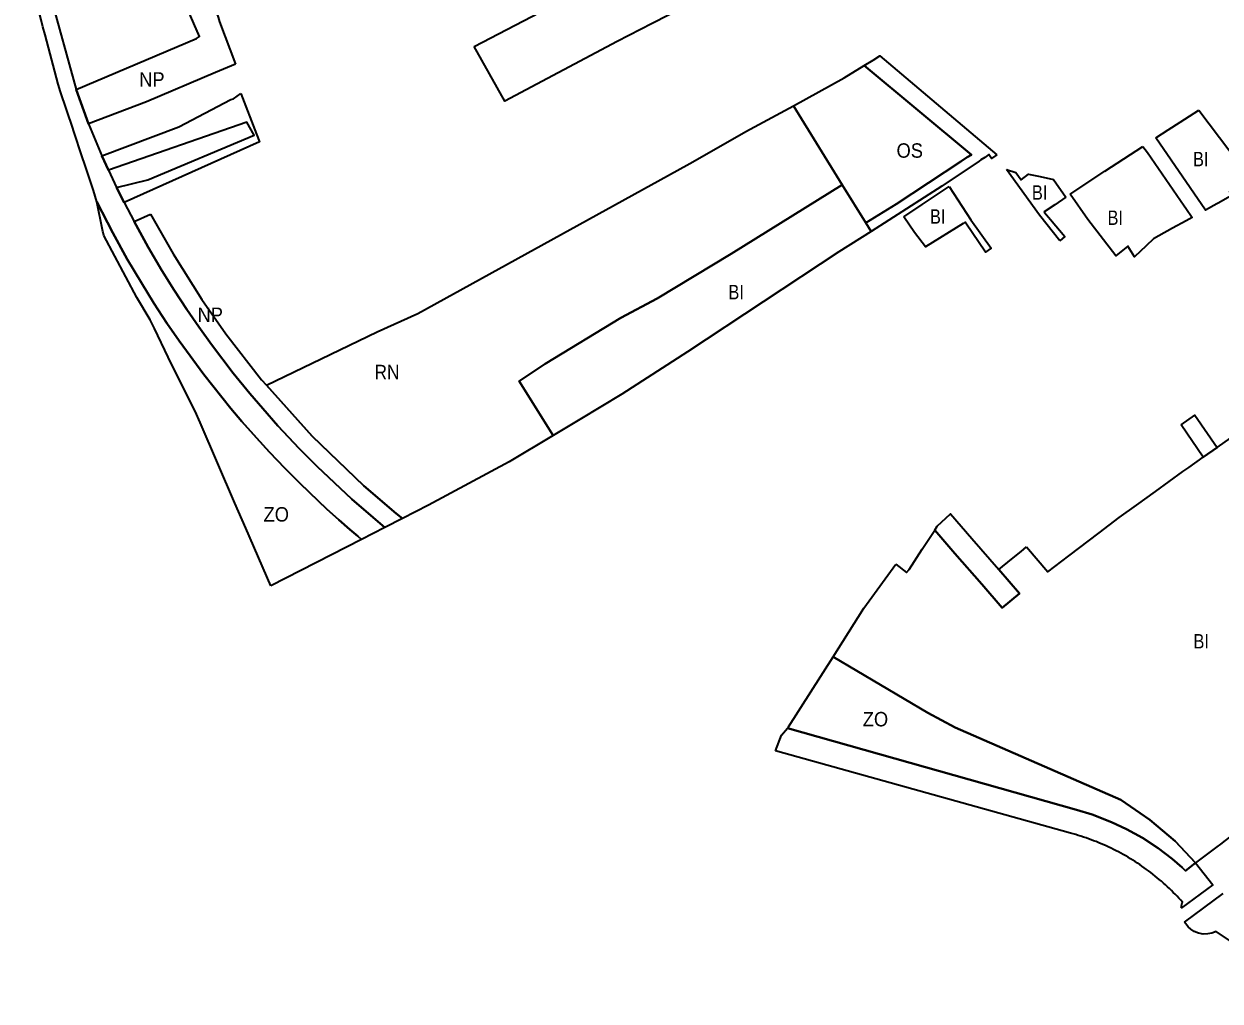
# Model space of a CAD drawing. Extents: x -650971 to -642489, y -1074311 to -1062745.
# Drawn here: x -649069 to -648072, y -1071514 to -1070700 of the extents above; entities that cross this region are included whole.
import ezdxf

# ---------------------------------------------------------------- set-up
doc = ezdxf.new("R2010")
doc.units = 0
doc.header["$LTSCALE"] = 4.8
for name, color, linetype, lineweight in [('15', 7, 'Continuous', 35), ('2', 7, 'Continuous', 35), ('24', 7, 'Continuous', 35), ('42', 7, 'Continuous', 35), ('48', 7, 'Continuous', 35), ('62', 7, 'Continuous', 35), ('7', 7, 'Continuous', 35), ('9', 7, 'Continuous', 35)]:
    doc.layers.add(name, color=color, linetype=linetype, lineweight=lineweight)

msp = doc.modelspace()

# ---------------------------------------------------------------- linework, layer by layer
at = {"layer": '15'}
for points in [[(-648368.163, -1070734.376), (-648360.83, -1070729.87), (-648355.275, -1070726.455), (-648257.61, -1070808.91)], [(-648366.98, -1070865.44), (-648341.58, -1070849.98), (-648287.74, -1070814.32), (-648282.44, -1070810.84), (-648278.832, -1070808.761), (-648368.163, -1070734.376)], [(-648257.61, -1070808.91), (-648262.15, -1070811.96), (-648264.38, -1070808.66), (-648267.8, -1070810.96), (-648271.1, -1070813.17), (-648272.453, -1070814.072), (-648272.45, -1070814.075), (-648303.631, -1070834.849), (-648362.519, -1070872.788), (-648366.98, -1070865.44)], [(-648309.41, -1071121.655), (-648307.33, -1071118.47), (-648296.34, -1071108.04), (-648278.39, -1071128.74), (-648256.04, -1071154.5)], [(-648256.04, -1071154.5), (-648238.84, -1071174.33), (-648253.126, -1071186.542), (-648270.236, -1071166.815), (-648292.587, -1071141.054), (-648309.41, -1071121.655)]]:
    msp.add_lwpolyline(points, dxfattribs=at)
msp.add_lwpolyline([(-648104.12, -1071033.78), (-648092.72, -1071025.89), (-648074.121, -1071052.749), (-648085.73, -1071060.92)], close=True, dxfattribs=at)
at = {"layer": '2'}
for points in [[(-648125.2, -1070794.79), (-648114.77, -1070788.08), (-648104.78, -1070781.65), (-648089.27, -1070771.57)], [(-648089.27, -1070771.57), (-648047.17, -1070827.35), (-648056.61, -1070834.26), (-648063.76, -1070839.49), (-648061.52, -1070842.68), (-648065.35, -1070844.8), (-648072.59, -1070848.79), (-648074.41, -1070849.79), (-648083.65, -1070854.89), (-648125.2, -1070794.79)], [(-648196.65, -1070841.7), (-648167.6, -1070822.53), (-648151.77, -1070812.11), (-648136.08, -1070801.79)], [(-648136.08, -1070801.79), (-648132.03, -1070807.05), (-648101.45, -1070851.34), (-648100, -1070853.35), (-648094.9, -1070861.09), (-648099.85, -1070863.82), (-648111.24, -1070870.11), (-648122.72, -1070876.44), (-648127, -1070878.75), (-648133.14, -1070884.6), (-648142.79, -1070893.78), (-648148.34, -1070884.92), (-648158.58, -1070892.98), (-648181.75, -1070862.74), (-648196.65, -1070841.7)], [(-648249.5, -1070821.08), (-648241.96, -1070823.46), (-648237.46, -1070829.68), (-648231.22, -1070824.92), (-648221.58, -1070827.03), (-648210.517, -1070829.445), (-648200.17, -1070844.094)], [(-648205.18, -1070880.5), (-648222.158, -1070859.221), (-648249.5, -1070821.08)], [(-648627.39, -1071042.65), (-648655.76, -1070997.5), (-648634.07, -1070983.17), (-648571.14, -1070944.67), (-648540.7, -1070928.6), (-648479.18, -1070891.26), (-648386.587, -1070833.807), (-648366.98, -1070865.44), (-648362.519, -1070872.788)], [(-648335.19, -1070860.49), (-648320.02, -1070850.16), (-648297.39, -1070835.36)], [(-648297.39, -1070835.36), (-648279.39, -1070862.98), (-648262.4, -1070886.58), (-648267.24, -1070889.9), (-648283.46, -1070865.74), (-648284.02, -1070864.91), (-648285.72, -1070865.96), (-648317.14, -1070885.48), (-648326.41, -1070873.55), (-648335.19, -1070860.49)], [(-648200.17, -1070844.094), (-648209.37, -1070850.44), (-648218.11, -1070856.44), (-648217.85, -1070856.93), (-648212.94, -1070862.74), (-648200.86, -1070877.05), (-648205.18, -1070880.5)], [(-648362.519, -1070872.788), (-648389.33, -1070889.79), (-648515.46, -1070972.94), (-648570.23, -1071008.2), (-648605.3, -1071029.34), (-648627.39, -1071042.65)], [(-648074.121, -1071052.749), (-648062.53, -1071044.59), (-648051.48, -1071036.97), (-648044.82, -1071032.25), (-648030.24, -1071021.91), (-648008.34, -1071006.32), (-647988.81, -1070993.27), (-647970.19, -1070980.45), (-647952.01, -1070967.82), (-647934.9, -1070955.87), (-647913.45, -1070940.79)], [(-648232.8, -1071135.6), (-648215.08, -1071156.35), (-648197.57, -1071143.03), (-648172.48, -1071123.95), (-648155.77, -1071111.23), (-648141.12, -1071100.71), (-648125.53, -1071089.51), (-648102.55, -1071072.86), (-648097.61, -1071069.37), (-648085.73, -1071060.92), (-648074.121, -1071052.749)], [(-648341.943, -1071150.071), (-648333.002, -1071157.07), (-648330.78, -1071154.36), (-648319.77, -1071137.52), (-648309.41, -1071121.655)], [(-648309.41, -1071121.655), (-648292.587, -1071141.054), (-648270.236, -1071166.815), (-648253.126, -1071186.542), (-648238.84, -1071174.33), (-648256.04, -1071154.5), (-648245.49, -1071145.91)], [(-648245.49, -1071145.91), (-648237.46, -1071139.38), (-648232.8, -1071135.6)], [(-648394.104, -1071227.17), (-648368.48, -1071186.81), (-648341.943, -1071150.071)], [(-648091.92, -1071399.07), (-648109, -1071381), (-648130, -1071363), (-648154.21, -1071346.477), (-648292.406, -1071286.112), (-648315.127, -1071274.052), (-648394.104, -1071227.17)], [(-647965.26, -1071302.86), (-647994.31, -1071325.03), (-648009.31, -1071336.48), (-648025.39, -1071348.76), (-648038.18, -1071358.51), (-648060.01, -1071374.69), (-648067.27, -1071380.27), (-648071.17, -1071383.26), (-648074.27, -1071385.62), (-648091.92, -1071399.07)]]:
    msp.add_lwpolyline(points, dxfattribs=at)
at = {"layer": '24'}
msp.add_line((-648101.203, -1071448.31), (-648069.022, -1071424.443), dxfattribs=at)
for points in [[(-649068.65, -1070642.23), (-649057.338, -1070637.689), (-649050.081, -1070663.981), (-649047.11, -1070674.743), (-649025.129, -1070754.377), (-649014.888, -1070782.994), (-649003.641, -1070809.566), (-648998.132, -1070821.723), (-648991.386, -1070835.954), (-648985.145, -1070848.538), (-648976.834, -1070864.527)], [(-649007.885, -1070848.153), (-649010.67, -1070838.5), (-649011.24, -1070836.79), (-649018.48, -1070815.18), (-649019.48, -1070812.18), (-649027.64, -1070787.8), (-649027.74, -1070787.51), (-649038.416, -1070755.66), (-649039.06, -1070753.72), (-649040.03, -1070750.06), (-649051.03, -1070708.74), (-649052.77, -1070702.25), (-649054.31, -1070696.44), (-649068.65, -1070642.23)], [(-648787.207, -1071129.363), (-648790.23, -1071126.818), (-648797, -1071121), (-648806.239, -1071112.938), (-648816.379, -1071103.782), (-648823.087, -1071097.562), (-648838.696, -1071082.562), (-648851.175, -1071069.886), (-648863.847, -1071056.723), (-648874.793, -1071044.773), (-648886.874, -1071031.044), (-648896.068, -1071020.184), (-648918.601, -1070991.969), (-648939.232, -1070963.818), (-648949.389, -1070949.031), (-648960.268, -1070932.429), (-648970.712, -1070915.663), (-648982.467, -1070895.704), (-648994.464, -1070873.974), (-649007.885, -1070848.153)], [(-648976.834, -1070864.527), (-648965.093, -1070885.794), (-648953.605, -1070905.299), (-648943.414, -1070921.659), (-648932.78, -1070937.887), (-648922.92, -1070952.242), (-648912.396, -1070966.893), (-648894.164, -1070990.806), (-648880.44, -1071007.703), (-648869.629, -1071020.411), (-648856.883, -1071034.761), (-648839.273, -1071053.556), (-648824.292, -1071068.677), (-648795.407, -1071095.8), (-648777.651, -1071111.23), (-648771.725, -1071116.233), (-648767.824, -1071119.455), (-648787.207, -1071129.363)], [(-648442.191, -1071305.453), (-648437.16, -1071292.53), (-648432.093, -1071286.645)], [(-648432.093, -1071286.645), (-648191.25, -1071354.858), (-648178.158, -1071358.781), (-648162.084, -1071364.918), (-648149.571, -1071370.788), (-648136.263, -1071378.194), (-648123.313, -1071386.696), (-648111.646, -1071395.618), (-648103.268, -1071402.88), (-648100.438, -1071405.517), (-648091.92, -1071399.07), (-648077.53, -1071417.4), (-648103.894, -1071436.837)], [(-648103.894, -1071436.837), (-648103.879, -1071436.624), (-648103.842, -1071436.2), (-648103.808, -1071435.882), (-648103.769, -1071435.565), (-648103.725, -1071435.248), (-648103.659, -1071434.826), (-648103.603, -1071434.511), (-648103.563, -1071434.301), (-648103.477, -1071433.883), (-648103.406, -1071433.571), (-648103.326, -1071433.244), (-648103.25, -1071432.951), (-648103.165, -1071432.642), (-648103.075, -1071432.336), (-648102.98, -1071432.031), (-648102.88, -1071431.729), (-648104.377, -1071430.062), (-648105.895, -1071428.411), (-648107.436, -1071426.776), (-648108.998, -1071425.156), (-648110.582, -1071423.554), (-648112.187, -1071421.967), (-648113.813, -1071420.397), (-648115.459, -1071418.845), (-648117.126, -1071417.311), (-648118.813, -1071415.795), (-648120.519, -1071414.298), (-648122.245, -1071412.82), (-648123.99, -1071411.361), (-648125.754, -1071409.922), (-648127.536, -1071408.504), (-648129.337, -1071407.106), (-648131.155, -1071405.729), (-648132.991, -1071404.373), (-648134.843, -1071403.038), (-648136.713, -1071401.725), (-648138.598, -1071400.435), (-648140.5, -1071399.167), (-648142.417, -1071397.922), (-648144.349, -1071396.699), (-648146.295, -1071395.5), (-648148.256, -1071394.325), (-648150.231, -1071393.173), (-648152.219, -1071392.046), (-648154.219, -1071390.942), (-648156.233, -1071389.864), (-648158.258, -1071388.809), (-648160.295, -1071387.78), (-648162.343, -1071386.776), (-648164.402, -1071385.797), (-648166.471, -1071384.843), (-648168.549, -1071383.915), (-648170.637, -1071383.013), (-648172.733, -1071382.137), (-648174.838, -1071381.286), (-648176.951, -1071380.462), (-648179.071, -1071379.664), (-648181.197, -1071378.891), (-648183.331, -1071378.146), (-648185.47, -1071377.426), (-648187.614, -1071376.733), (-648189.763, -1071376.067), (-648191.917, -1071375.427), (-648194.075, -1071374.813), (-648196.236, -1071374.226), (-648442.191, -1071305.453)], [(-647986.233, -1071514.148), (-648021.015, -1071492.264), (-648027.562, -1071487.894), (-648074.86, -1071456.248), (-648078.539, -1071457.636), (-648081.642, -1071458.215), (-648085.585, -1071458.248), (-648089.539, -1071457.489), (-648093.059, -1071456.066), (-648096.014, -1071454.192), (-648098.259, -1071452.196), (-648101.203, -1071448.31)]]:
    msp.add_lwpolyline(points, dxfattribs=at)
at = {"layer": '42'}
for points in [[(-649007.885, -1070848.153), (-648994.464, -1070873.974), (-648982.467, -1070895.704), (-648970.712, -1070915.663), (-648960.268, -1070932.429), (-648949.389, -1070949.031), (-648939.232, -1070963.818), (-648918.601, -1070991.969), (-648896.068, -1071020.184), (-648886.874, -1071031.044), (-648874.793, -1071044.773), (-648863.847, -1071056.723), (-648851.175, -1071069.886), (-648838.696, -1071082.562), (-648823.087, -1071097.562), (-648816.379, -1071103.782), (-648806.239, -1071112.938), (-648797, -1071121), (-648790.23, -1071126.818), (-648787.207, -1071129.363), (-648862.97, -1071168.09)], [(-648862.97, -1071168.09), (-648883.73, -1071120.13), (-648892.82, -1071099.15), (-648921.87, -1071032.04), (-648922.98, -1071029.49), (-648924.92, -1071024.89), (-648948.29, -1070977.37), (-648959.92, -1070953.73), (-648963.5, -1070946.45), (-648974.4, -1070927.77), (-649002.15, -1070875.96), (-649002.62, -1070873.69), (-649002.82, -1070872.69), (-649003.1, -1070871.35), (-649007.885, -1070848.153)], [(-648432.093, -1071286.645), (-648431.21, -1071285.62), (-648394.104, -1071227.17)], [(-648394.104, -1071227.17), (-648315.127, -1071274.052), (-648292.406, -1071286.112), (-648154.21, -1071346.477), (-648130, -1071363), (-648109, -1071381), (-648091.92, -1071399.07)], [(-648091.92, -1071399.07), (-648100.438, -1071405.517), (-648103.268, -1071402.88), (-648111.646, -1071395.618), (-648123.313, -1071386.696), (-648136.263, -1071378.194), (-648149.571, -1071370.788), (-648162.084, -1071364.918), (-648178.158, -1071358.781), (-648191.25, -1071354.858), (-648432.093, -1071286.645)]]:
    msp.add_lwpolyline(points, dxfattribs=at)
at = {"layer": '48'}
msp.add_line((-648976.834, -1070864.527), (-648963.107, -1070858.328), dxfattribs=at)
for points in [[(-648941.064, -1070599.735), (-648927.141, -1070638.141), (-648906.79, -1070694.25), (-648905.65, -1070698.06), (-648892.215, -1070733.293)], [(-649025.129, -1070754.377), (-648924.668, -1070712.022), (-648922.196, -1070710.207), (-648952.455, -1070640.564), (-649047.11, -1070674.743), (-649050.081, -1070663.981)], [(-648892.215, -1070733.293), (-648908.94, -1070740.19), (-648966.35, -1070764.7), (-649014.888, -1070782.994), (-649025.129, -1070754.377)], [(-649003.641, -1070809.566), (-648939.5, -1070785.4), (-648896.11, -1070762.73), (-648894.08, -1070762.22), (-648887.84, -1070757.84)], [(-648887.84, -1070757.84), (-648874.87, -1070791.61), (-648872.375, -1070798.112), (-648985.145, -1070848.538), (-648991.386, -1070835.954)], [(-648991.386, -1070835.954), (-648965.475, -1070829.829), (-648876.64, -1070792.6), (-648882.919, -1070781.673), (-648998.132, -1070821.723), (-649003.641, -1070809.566)], [(-648963.107, -1070858.328), (-648944.376, -1070891.404), (-648920.293, -1070929.567), (-648900.337, -1070957.964), (-648870.479, -1070996.265), (-648866.341, -1071000.881)], [(-648767.824, -1071119.455), (-648771.725, -1071116.233), (-648777.651, -1071111.23), (-648795.407, -1071095.8), (-648824.292, -1071068.677), (-648839.273, -1071053.556), (-648856.883, -1071034.761), (-648869.629, -1071020.411), (-648880.44, -1071007.703), (-648894.164, -1070990.806), (-648912.396, -1070966.893), (-648922.92, -1070952.242), (-648932.78, -1070937.887), (-648943.414, -1070921.659), (-648953.605, -1070905.299), (-648965.093, -1070885.794), (-648976.834, -1070864.527)], [(-648866.341, -1071000.881), (-648828.353, -1071043.265), (-648785.386, -1071084.634), (-648758.423, -1071107.756), (-648752.967, -1071111.861), (-648767.824, -1071119.455)]]:
    msp.add_lwpolyline(points, dxfattribs=at)
at = {"layer": '7'}
for points in [[(-648693.45, -1070718.46), (-648597.74, -1070668.62), (-648544.42, -1070639.42), (-648492.47, -1070614.2), (-648466.61, -1070600.21)], [(-648466.61, -1070600.21), (-648465.28, -1070602.24), (-648440.8, -1070639.72), (-648438.13, -1070644.73), (-648544.906, -1070699.451), (-648574.27, -1070714.5)], [(-648574.27, -1070714.5), (-648667.72, -1070764.15), (-648693.45, -1070718.46)], [(-648516.092, -1070817.462), (-648511.09, -1070814.7), (-648466.83, -1070789.54), (-648427.25, -1070767.95), (-648386.587, -1070833.807)], [(-648866.341, -1071000.881), (-648820.822, -1070978.778), (-648774.23, -1070956.42), (-648740.25, -1070941.21), (-648516.092, -1070817.462)], [(-648386.587, -1070833.807), (-648479.18, -1070891.26), (-648540.7, -1070928.6), (-648571.14, -1070944.67), (-648634.07, -1070983.17), (-648655.76, -1070997.5), (-648627.39, -1071042.65)], [(-648752.967, -1071111.861), (-648758.423, -1071107.756), (-648785.386, -1071084.634), (-648828.353, -1071043.265), (-648866.341, -1071000.881)], [(-648627.39, -1071042.65), (-648664.1, -1071064.78), (-648731.27, -1071100.77), (-648752.967, -1071111.861)]]:
    msp.add_lwpolyline(points, dxfattribs=at)
at = {"layer": '9'}
for points in [[(-648427.25, -1070767.95), (-648385.03, -1070744.74), (-648368.163, -1070734.376)], [(-648368.163, -1070734.376), (-648278.832, -1070808.761), (-648282.44, -1070810.84), (-648287.74, -1070814.32), (-648341.58, -1070849.98), (-648366.98, -1070865.44), (-648386.587, -1070833.807), (-648427.25, -1070767.95)]]:
    msp.add_lwpolyline(points, dxfattribs=at)

# ---------------------------------------------------------------- texts
at = {"layer": '62'}
for s, width, p in [('NP', 0.95, (-648972.583, -1070752.041)), ('OS', 0.95, (-648341.265, -1070811.272)), ('BI', 0.85, (-648094.127, -1070818.398)), ('BI', 0.85, (-648228.397, -1070846.265)), ('BI', 0.85, (-648313.397, -1070866.265)), ('BI', 0.85, (-648165.397, -1070867.265)), ('BI', 0.85, (-648481.397, -1070929.265)), ('NP', 0.95, (-648923.942, -1070948.157)), ('RN', 0.9, (-648776.428, -1070995.883)), ('ZO', 0.95, (-648868.886, -1071114.486)), ('BI', 0.85, (-648093.764, -1071220.263)), ('ZO', 0.95, (-648369.423, -1071285.188))]:
    msp.add_text(s, height=12, dxfattribs=dict(at, width=width)).set_placement(p)

doc.saveas('drawing.dxf')
